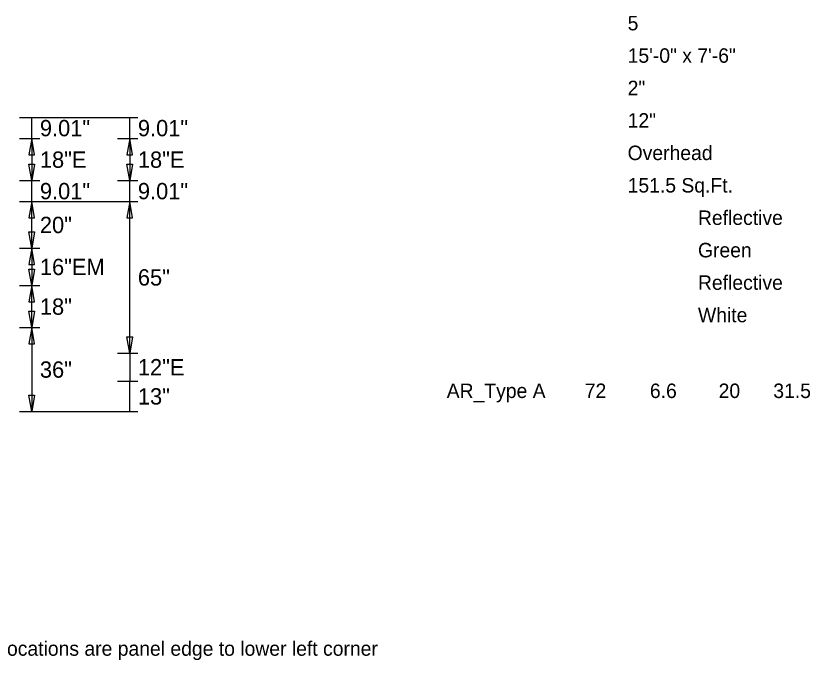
# Model space of a CAD drawing. Extents: x 2149934 to 2150188, y 145113 to 145238.
# Drawn here: x 2149977 to 2150005.37, y 145187.81 to 145210.83 of the extents above; entities that cross this region are included whole.
import ezdxf

# ---------------------------------------------------------------- set-up
doc = ezdxf.new("R2010")
doc.units = 0
for name, color, linetype in [('GSDIMS', 7, 'Continuous'), ('GSSHT', 7, 'Continuous'), ('Level 1', 7, 'Continuous')]:
    doc.layers.add(name, color=color, linetype=linetype)

msp = doc.modelspace()

# ---------------------------------------------------------------- linework, layer by layer
at = {"layer": 'GSDIMS'}
for p, q in [((2149977.125, 145207.196), (2149977.854, 145207.196)), ((2149977.125, 145207.196), (2149980.625, 145207.196)), ((2149977.562, 145206.445), (2149977.562, 145207.196)), ((2149980.625, 145207.196), (2149981.354, 145207.196)), ((2149981.062, 145206.445), (2149981.062, 145207.196)), ((2149977.125, 145206.445), (2149977.854, 145206.445)), ((2149977.125, 145206.445), (2149977.854, 145206.445)), ((2149977.562, 145206.445), (2149977.562, 145204.945)), ((2149980.625, 145206.445), (2149981.354, 145206.445)), ((2149980.625, 145206.445), (2149981.354, 145206.445)), ((2149981.062, 145206.445), (2149981.062, 145204.945)), ((2149977.125, 145204.945), (2149977.854, 145204.945)), ((2149977.125, 145204.945), (2149977.854, 145204.945)), ((2149977.562, 145204.194), (2149977.562, 145204.945)), ((2149980.625, 145204.945), (2149981.354, 145204.945)), ((2149980.625, 145204.945), (2149981.354, 145204.945)), ((2149981.062, 145204.194), (2149981.062, 145204.945)), ((2149977.124, 145204.195), (2149977.854, 145204.195)), ((2149977.124, 145204.195), (2149980.624, 145204.195)), ((2149977.125, 145204.194), (2149977.854, 145204.194)), ((2149977.125, 145204.194), (2149980.625, 145204.194)), ((2149977.562, 145202.528), (2149977.562, 145204.195)), ((2149980.624, 145204.195), (2149981.354, 145204.195)), ((2149980.625, 145204.194), (2149981.354, 145204.194)), ((2149981.062, 145198.778), (2149981.062, 145204.195)), ((2149977.124, 145202.528), (2149977.854, 145202.528)), ((2149977.124, 145202.528), (2149977.854, 145202.528)), ((2149977.562, 145202.528), (2149977.562, 145201.195)), ((2149977.124, 145201.195), (2149977.854, 145201.195)), ((2149977.124, 145201.195), (2149977.854, 145201.195)), ((2149977.562, 145199.695), (2149977.562, 145201.195)), ((2149977.124, 145199.695), (2149977.854, 145199.695)), ((2149977.124, 145199.695), (2149977.854, 145199.695)), ((2149977.562, 145199.695), (2149977.562, 145196.695)), ((2149980.624, 145198.778), (2149981.354, 145198.778)), ((2149980.624, 145198.778), (2149981.354, 145198.778)), ((2149981.062, 145198.778), (2149981.062, 145197.778)), ((2149980.624, 145197.778), (2149981.354, 145197.778)), ((2149980.624, 145197.778), (2149981.354, 145197.778)), ((2149981.062, 145196.695), (2149981.062, 145197.778)), ((2149977.124, 145196.695), (2149977.854, 145196.695)), ((2149977.124, 145196.695), (2149980.624, 145196.695)), ((2149980.624, 145196.695), (2149981.354, 145196.695))]:
    msp.add_line(p, q, dxfattribs=at)
for points in [[(2149977.562, 145206.445), (2149977.465, 145205.862), (2149977.659, 145205.862)], [(2149981.062, 145206.445), (2149980.965, 145205.862), (2149981.159, 145205.862)], [(2149977.562, 145204.945), (2149977.465, 145205.528), (2149977.659, 145205.528)], [(2149981.062, 145204.945), (2149980.965, 145205.528), (2149981.159, 145205.528)], [(2149977.562, 145204.195), (2149977.465, 145203.611), (2149977.659, 145203.611)], [(2149981.062, 145204.195), (2149980.965, 145203.611), (2149981.159, 145203.611)], [(2149977.562, 145202.528), (2149977.465, 145203.112), (2149977.659, 145203.112)], [(2149977.562, 145202.528), (2149977.465, 145201.945), (2149977.659, 145201.945)], [(2149977.562, 145201.195), (2149977.465, 145201.778), (2149977.659, 145201.778)], [(2149977.562, 145201.195), (2149977.465, 145200.612), (2149977.659, 145200.612)], [(2149977.562, 145199.695), (2149977.465, 145200.278), (2149977.659, 145200.278)], [(2149977.562, 145199.695), (2149977.465, 145199.112), (2149977.659, 145199.112)], [(2149981.062, 145198.778), (2149980.965, 145199.362), (2149981.159, 145199.362)], [(2149977.562, 145196.695), (2149977.465, 145197.278), (2149977.659, 145197.278)]]:
    msp.add_lwpolyline(points, close=True, dxfattribs=at)

# ---------------------------------------------------------------- texts
for s, p in [('9.01"', (2149977.854, 145206.529)), ('9.01"', (2149981.354, 145206.529)), ('18"E', (2149977.854, 145205.403)), ('18"E', (2149981.354, 145205.403)), ('9.01"', (2149977.854, 145204.278)), ('9.01"', (2149981.354, 145204.278)), ('20"', (2149977.854, 145203.07)), ('16"EM', (2149977.854, 145201.57)), ('65"', (2149981.354, 145201.195)), ('18"', (2149977.854, 145200.153)), ('36"', (2149977.854, 145197.903)), ('12"E', (2149981.354, 145197.987)), ('13"', (2149981.354, 145196.945))]:
    msp.add_text(s, height=0.5833, dxfattribs=at).set_placement(p)
at = {"layer": 'GSSHT'}
for s, height, p in [('5', 0.517, (2149998.849, 145210.315)), ('Overhead', 0.5165, (2149998.849, 145205.679))]:
    msp.add_text(s, height=height, dxfattribs=at).set_placement(p)
at = {"layer": 'Level 1'}
for s, height, p in [('15\'-0" x 7\'-6"', 0.51652, (2149998.849, 145209.156)), ('2"', 0.5165, (2149998.849, 145207.997)), ('12"', 0.5165, (2149998.849, 145206.838)), ('151.5 Sq.Ft.', 0.51652, (2149998.849, 145204.52)), ('Reflective', 0.5165, (2150001.361, 145203.361)), ('Green', 0.5165, (2150001.361, 145202.203)), ('Reflective', 0.5165, (2150001.361, 145201.044)), ('White', 0.5165, (2150001.361, 145199.885)), ('AR_Type A', 0.5165, (2149992.386, 145197.177)), ('72', 0.5165, (2149997.317, 145197.177)), ('6.6', 0.5165, (2149999.644, 145197.177)), ('20', 0.5165, (2150002.099, 145197.177)), ('31.5', 0.5165, (2150004.052, 145197.177)), ('Letter locations are panel edge to lower left corner', 0.51652, (2149974.568, 145187.968))]:
    msp.add_text(s, height=height, dxfattribs=at).set_placement(p)

doc.saveas('drawing.dxf')
